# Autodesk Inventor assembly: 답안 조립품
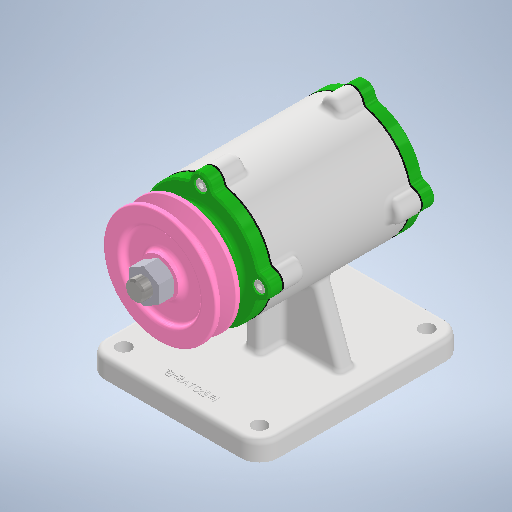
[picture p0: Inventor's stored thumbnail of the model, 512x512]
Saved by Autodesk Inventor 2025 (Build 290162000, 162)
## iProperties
Created: 2024-08
Part Number: 답안 조립품
Document SubType Name: Assembly
Designer: hsj03
Author: hsj03
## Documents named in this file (12)
- C:\Users\hsj03\OneDrive\바탕 화면\740807V1008\답안 조립품.iam
- C:\Users\hsj03\OneDrive\바탕 화면\740807V1008\부품.ipt
- C:\Users\hsj03\OneDrive\바탕 화면\740807V1008\V-벨트풀리\V-벨트풀리.ipt
- C:\Users\hsj03\OneDrive\바탕 화면\740807V1008\개스킷\개스킷.ipt
- C:\Users\hsj03\OneDrive\바탕 화면\740807V1008\너트 M12 x 1.25\너트 M12 x 1.25.ipt
- C:\Users\hsj03\OneDrive\바탕 화면\740807V1008\뒤커버\뒤커버.ipt
- C:\Users\hsj03\OneDrive\바탕 화면\740807V1008\베어링 6204\베어링 6204.ipt
- C:\Users\hsj03\OneDrive\바탕 화면\740807V1008\볼트 M4 x 12\볼트 M4 x 12.ipt
- C:\Users\hsj03\OneDrive\바탕 화면\740807V1008\앞커버\앞커버.ipt
- C:\Users\hsj03\OneDrive\바탕 화면\740807V1008\오일실\오일실.ipt
- C:\Users\hsj03\OneDrive\바탕 화면\740807V1008\축\축.ipt
- C:\Users\hsj03\OneDrive\바탕 화면\740807V1008\키 4 x 4\키 4 x 4.ipt
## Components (3 placed, 2 different names)
1. V-벨트풀리:1
2. 개스킷:1
3. 개스킷:2
